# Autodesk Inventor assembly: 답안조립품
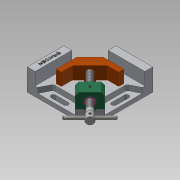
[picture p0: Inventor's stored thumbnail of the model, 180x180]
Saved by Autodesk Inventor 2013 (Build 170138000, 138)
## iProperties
Created: 2019-04
Part Number: 답안조립품
Document SubType Name: Assembly
Designer: Administrator
Author: Administrator
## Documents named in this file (11)
- C:\Users\Administrator\Desktop\490407V1010\답안조립품.iam
- C:\Users\Administrator\Desktop\490407V1010\베이스.ipt
- C:\Users\Administrator\Desktop\490407V1010\리드스크류.ipt
- C:\Users\Administrator\Desktop\490407V1010\멈춤나사 M4x5.ipt
- C:\Users\Administrator\Desktop\490407V1010\멈춤나사 M4x10.ipt
- C:\Users\Administrator\Desktop\490407V1010\볼트 M4x16.ipt
- C:\Users\Administrator\Desktop\490407V1010\부시.ipt
- C:\Users\Administrator\Desktop\490407V1010\서포트.ipt
- C:\Users\Administrator\Desktop\490407V1010\조.ipt
- C:\Users\Administrator\Desktop\490407V1010\평행 핀 2.5x24.ipt
- C:\Users\Administrator\Desktop\490407V1010\핸들.ipt
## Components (1 placed, 1 different names)
1. 핸들:1
